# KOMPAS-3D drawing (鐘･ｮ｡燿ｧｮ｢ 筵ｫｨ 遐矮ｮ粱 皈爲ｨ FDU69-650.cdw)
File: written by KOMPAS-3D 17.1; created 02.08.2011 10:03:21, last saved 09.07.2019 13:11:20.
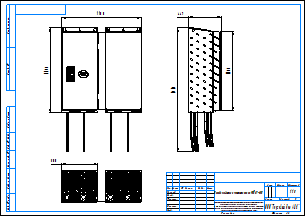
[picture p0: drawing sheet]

Title block, sheet 1: name: Преобразователи частоты серии FDU69-650; scale: 1:10; sheets: 1; sheet format: A3; stored path: \\adlc.lan\data\АДЛ_ПКД\3D-модели\Поставщики\Оборудование Emotron\Преобразователи частоты\Серия FDU 2.0\KOMPAS 2D\Преобразователи частоты серии FDU69-650.cdw

Views: Спереди 1
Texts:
  Рама для чертежей
  Лит-Масса-Масштаб
  Материал-Предприятие
  Масштаб
  Изм.
  Лист
  № докум.
  Подп.
  Дата
  Лит.
  Разраб.
  Пров.
  Т.контр.
  Листов
  Внимание! Данный продукт является объектом авторского права ООО «Торговый Дом АДЛ».
  Запрещается изменение, копирование, распространение
  (в том числе путем копирования на другие сайты и ресурсы в Интернете)
  или любое иное использование информации и объектов без предварительного
  согласия правообладателя (ООО «Торговый Дом АДЛ»).
  Н.контр.
  Утв.
  ООО "Торговый дом АДЛ"
  Изменение
  Номер документа
  Подпись
  Обозначение документа
  Наименование изделия
  Масса изделия по ГОСТ 2.109-73
  Порядковый номер листа
  Общее количество листов в документе
  Характер работы, выполненной лицом, подписавшим документ
  Наименование или индекс предприятия, выпускающего документ
  Инв. № подл.
  Подп. и дата
  Взам. инв. №
  Инв. № дубл.
  Инвентарный номер подлинника по ГОСТ 2.501-68
  Подпись принявшего подлинник в отдел технической документации
  Инвентарный номер подлинника, взамен которого выпущен данный подлинник
  Инвентарный номер дубликата по ГОСТ 2.502-68
  Подпись принявшего дубликат в отдел технической документации
  Справ. №
  Перв. примен.
  Обозначение документа, взамен или на основании которого выпущен данный документ
  Обозначение документа, в котором впервые записан данный документ
  Подпись лица, копировавшего чертеж
  Обозначение формата листа
  !Рама для чертежа
Dimensions and other numbers on the sheet: 1100; 1176; 449; 500; 1718; 1:10; 1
